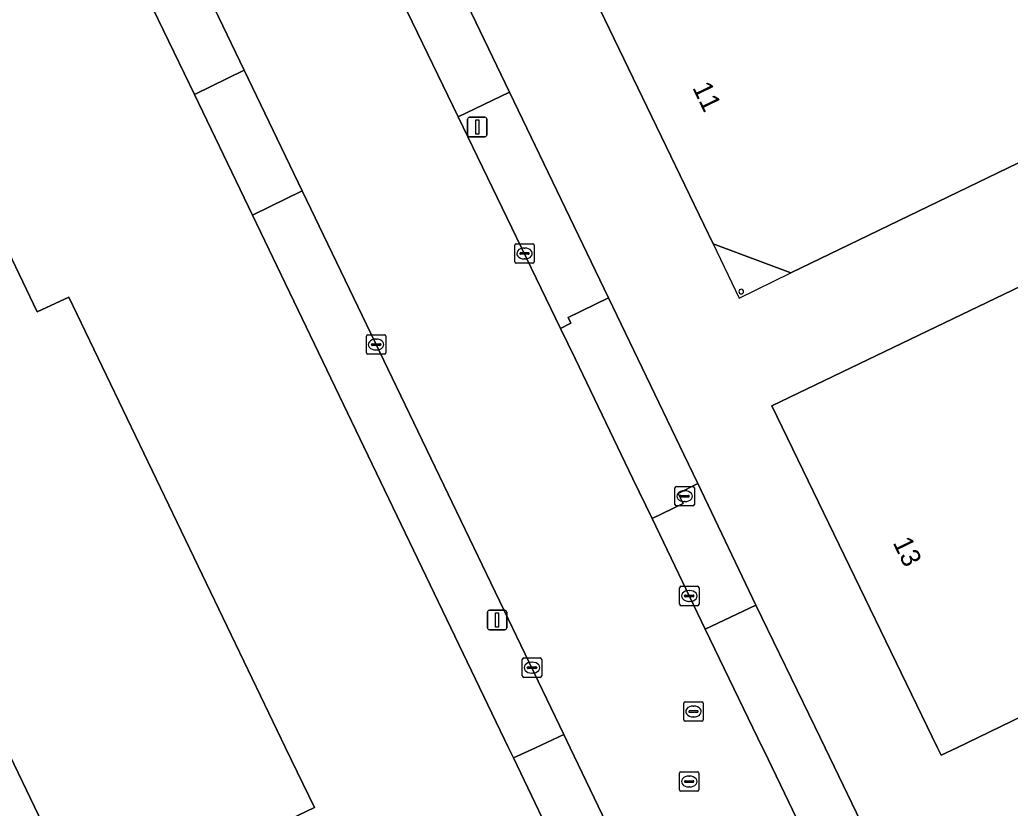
# Model space of a CAD drawing. Extents: x 157692 to 159674, y 381452 to 383291.
# Drawn here: x 158074.3 to 158125.3, y 381746.9 to 381787.5 of the extents above; entities that cross this region are included whole.
import ezdxf

# ---------------------------------------------------------------- set-up
doc = ezdxf.new("R2010")
doc.units = 0
for name, color, linetype in [('IMGEO_Brandkraan', 7, 'Continuous'), ('IMGEO_Erf', 7, 'Continuous'), ('IMGEO_Kolk', 7, 'Continuous'), ('IMGEO_Lichtmast', 7, 'Continuous'), ('IMGEO_Pand', 7, 'Continuous'), ('IMGEO_Pand_nummerreeks', 7, 'Continuous'), ('IMGEO_Pand_overbouw', 7, 'Continuous'), ('IMGEO_Rijbaan_lokaal_gesloten', 7, 'Continuous'), ('IMGEO_Rioolput', 7, 'Continuous'), ('IMGEO_Voetpad_open', 7, 'Continuous')]:
    doc.layers.add(name, color=color, linetype=linetype)

msp = doc.modelspace()

# ---------------------------------------------------------------- linework, layer by layer
at = {"layer": 'IMGEO_Brandkraan'}
for p, q in [((158108.057, 381762.52), (158108.057, 381763.372)), ((158108.132, 381763.446), (158108.984, 381763.446)), ((158108.545, 381763.226), (158108.57, 381763.226)), ((158109.058, 381763.372), (158109.058, 381762.52)), ((158108.316, 381762.94), (158108.316, 381762.952)), ((158108.754, 381762.903), (158108.356, 381762.903)), ((158108.359, 381762.989), (158108.757, 381762.989)), ((158108.568, 381762.666), (158108.543, 381762.666)), ((158108.8, 381762.952), (158108.8, 381762.94)), ((158108.984, 381762.446), (158108.132, 381762.446))]:
    msp.add_line(p, q, dxfattribs=at)
for points in [[(158108.057, 381762.52), (158108.057, 381763.372)], [(158108.132, 381763.446), (158108.984, 381763.446)], [(158109.058, 381763.372), (158109.058, 381762.52)], [(158108.984, 381762.446), (158108.132, 381762.446)]]:
    msp.add_lwpolyline(points, dxfattribs=at)
for centre, radius, start, end in [((158108.134, 381763.37), 0.0765, 91.552, 178.448), ((158108.134, 381763.37), 0.0765, 91.552, 178.448), ((158108.982, 381763.37), 0.0765, 1.552, 88.448), ((158108.982, 381763.37), 0.0765, 1.552, 88.448), ((158108.356, 381762.949), 0.0403, 85.8775, 175.7526), ((158108.353, 381762.939), 0.0366, 178.938, 274.7102), ((158108.757, 381762.946), 0.043, 264.8664, 352.4533), ((158108.761, 381762.951), 0.0386, 1.7309, 96.639), ((158108.134, 381762.522), 0.0765, 181.552, 268.448), ((158108.134, 381762.522), 0.0765, 181.552, 268.448), ((158108.982, 381762.522), 0.0765, 271.552, 358.448), ((158108.982, 381762.522), 0.0765, 271.552, 358.448)]:
    msp.add_arc(centre, radius, start, end, dxfattribs=at)
for centre, major_axis, ratio, start_param, end_param in [((158108.544, 381762.946), (-0.387, 0.002), 0.722429, 4.712389, 7.853982), ((158108.569, 381762.946), (-0.39, 0.002), 0.717154, 1.570796, 4.712389)]:
    msp.add_ellipse(centre, major_axis=major_axis, ratio=ratio, start_param=start_param, end_param=end_param, dxfattribs=at)
at = {"layer": 'IMGEO_Erf'}
for points in [[(158137.502, 381785.79), (158118.534, 381776.617), (158114.031, 381774.441), (158110.021, 381775.933), (158102.507, 381791.513), (158111.619, 381795.703), (158111.472, 381796), (158115.756, 381798.065), (158110.472, 381809.1), (158104.602, 381810.258), (158098.579, 381811.447), (158101.581, 381826.071)], [(158092.487, 381798.744), (158092.916, 381798.939), (158095.512, 381792.931), (158095.193, 381792.79), (158096.925, 381789.189), (158099.538, 381783.755), (158104.632, 381773.16), (158105.509, 381771.337), (158108.516, 381765.1), (158109.23, 381763.603), (158112.225, 381757.328), (158115.269, 381751.09), (158115.795, 381750), (158119.248, 381742.84), (158125.511, 381729.855), (158128.564, 381723.514), (158130.19, 381720.284), (158133.095, 381714.162), (158136.569, 381706.935)], [(158006.881, 381609.083), (158005.905, 381627.867), (158005.466, 381636.382), (158005.223, 381641.106), (158032.78, 381654.365), (158038.282, 381657.004), (158060.573, 381667.757), (158067.21, 381670.951), (158069.612, 381672.132), (158075.377, 381674.875), (158095.213, 381684.451), (158107.373, 381690.341), (158121.318, 381697.1), (158122.884, 381701.311), (158109.399, 381729.267), (158106.88, 381734.578), (158102.545, 381743.606), (158102.331, 381744.049), (158099.751, 381749.471), (158099.496, 381750), (158086.302, 381777.417), (158083.311, 381783.632), (158080.659, 381789.142)], [(158127.079, 381752.164), (158122.572, 381750), (158121.766, 381749.613), (158121.578, 381750), (158113.047, 381767.596), (158117.554, 381769.761), (158139.912, 381780.502)], [(158073.743, 381775.528), (158075.215, 381772.432), (158076.855, 381773.194), (158088.009, 381750), (158089.492, 381746.916), (158077.795, 381741.308), (158073.628, 381750)]]:
    msp.add_lwpolyline(points, dxfattribs=at)
for start, end in [(0, 180), (180, 0)]:
    msp.add_arc((158111.475, 381773.48), 0.12, start, end, dxfattribs=at)
at = {"layer": 'IMGEO_Kolk'}
for p, q in [((158099.813, 381775.016), (158099.813, 381775.868)), ((158099.888, 381775.942), (158100.74, 381775.942)), ((158100.814, 381775.868), (158100.814, 381775.016)), ((158100.072, 381775.436), (158100.072, 381775.448)), ((158100.51, 381775.399), (158100.112, 381775.399)), ((158100.115, 381775.485), (158100.513, 381775.485)), ((158100.301, 381775.722), (158100.326, 381775.722)), ((158100.556, 381775.448), (158100.556, 381775.436)), ((158100.74, 381774.942), (158099.888, 381774.942)), ((158100.324, 381775.162), (158100.299, 381775.162)), ((158092.245, 381771.253), (158093.097, 381771.253)), ((158092.17, 381770.327), (158092.17, 381771.179)), ((158092.429, 381770.747), (158092.429, 381770.759)), ((158092.867, 381770.71), (158092.469, 381770.71)), ((158092.472, 381770.796), (158092.87, 381770.796)), ((158092.658, 381771.033), (158092.683, 381771.033)), ((158092.913, 381770.759), (158092.913, 381770.747)), ((158093.171, 381771.179), (158093.171, 381770.327)), ((158093.097, 381770.253), (158092.245, 381770.253)), ((158092.681, 381770.473), (158092.656, 381770.473)), ((158108.297, 381757.384), (158108.297, 381758.236)), ((158108.372, 381758.31), (158109.224, 381758.31)), ((158108.785, 381758.09), (158108.81, 381758.09)), ((158109.298, 381758.236), (158109.298, 381757.384)), ((158108.556, 381757.804), (158108.556, 381757.816)), ((158108.994, 381757.767), (158108.596, 381757.767)), ((158108.599, 381757.853), (158108.997, 381757.853)), ((158108.808, 381757.53), (158108.783, 381757.53)), ((158109.04, 381757.816), (158109.04, 381757.804)), ((158109.224, 381757.31), (158108.372, 381757.31)), ((158100.197, 381753.692), (158100.197, 381754.544)), ((158100.272, 381754.618), (158101.124, 381754.618)), ((158100.685, 381754.398), (158100.71, 381754.398)), ((158101.198, 381754.544), (158101.198, 381753.692)), ((158100.456, 381754.112), (158100.456, 381754.124)), ((158100.894, 381754.075), (158100.496, 381754.075)), ((158100.499, 381754.161), (158100.897, 381754.161)), ((158100.94, 381754.124), (158100.94, 381754.112)), ((158101.124, 381753.618), (158100.272, 381753.618)), ((158100.708, 381753.838), (158100.683, 381753.838))]:
    msp.add_line(p, q, dxfattribs=at)
for points in [[(158099.813, 381775.016), (158099.813, 381775.868)], [(158099.888, 381775.942), (158100.74, 381775.942)], [(158100.814, 381775.868), (158100.814, 381775.016)], [(158100.74, 381774.942), (158099.888, 381774.942)], [(158092.245, 381771.253), (158093.097, 381771.253)], [(158092.17, 381770.327), (158092.17, 381771.179)], [(158093.171, 381771.179), (158093.171, 381770.327)], [(158093.097, 381770.253), (158092.245, 381770.253)], [(158108.297, 381757.384), (158108.297, 381758.236)], [(158108.372, 381758.31), (158109.224, 381758.31)], [(158109.298, 381758.236), (158109.298, 381757.384)], [(158109.224, 381757.31), (158108.372, 381757.31)], [(158100.197, 381753.692), (158100.197, 381754.544)], [(158100.272, 381754.618), (158101.124, 381754.618)], [(158101.198, 381754.544), (158101.198, 381753.692)], [(158101.124, 381753.618), (158100.272, 381753.618)]]:
    msp.add_lwpolyline(points, dxfattribs=at)
for centre, radius, start, end in [((158099.89, 381775.866), 0.0765, 91.552, 178.448), ((158099.89, 381775.866), 0.0765, 91.552, 178.448), ((158100.738, 381775.866), 0.0765, 1.552, 88.448), ((158100.738, 381775.866), 0.0765, 1.552, 88.448), ((158100.112, 381775.445), 0.0403, 85.8775, 175.7526), ((158100.109, 381775.435), 0.0366, 178.938, 274.7102), ((158100.513, 381775.442), 0.043, 264.8664, 352.4533), ((158100.517, 381775.447), 0.0386, 1.7309, 96.639), ((158099.89, 381775.018), 0.0765, 181.552, 268.448), ((158099.89, 381775.018), 0.0765, 181.552, 268.448), ((158100.738, 381775.018), 0.0765, 271.552, 358.448), ((158100.738, 381775.018), 0.0765, 271.552, 358.448), ((158092.247, 381771.177), 0.0765, 91.552, 178.448), ((158092.247, 381771.177), 0.0765, 91.552, 178.448), ((158093.095, 381771.177), 0.0765, 1.552, 88.448), ((158093.095, 381771.177), 0.0765, 1.552, 88.448), ((158092.469, 381770.756), 0.0403, 85.8775, 175.7526), ((158092.466, 381770.746), 0.0366, 178.938, 274.7102), ((158092.87, 381770.753), 0.043, 264.8664, 352.4533), ((158092.874, 381770.758), 0.0386, 1.7309, 96.639), ((158092.247, 381770.329), 0.0765, 181.552, 268.448), ((158092.247, 381770.329), 0.0765, 181.552, 268.448), ((158093.095, 381770.329), 0.0765, 271.552, 358.448), ((158093.095, 381770.329), 0.0765, 271.552, 358.448), ((158108.374, 381758.234), 0.0765, 91.552, 178.448), ((158108.374, 381758.234), 0.0765, 91.552, 178.448), ((158109.222, 381758.234), 0.0765, 1.552, 88.448), ((158109.222, 381758.234), 0.0765, 1.552, 88.448), ((158108.596, 381757.813), 0.0403, 85.8775, 175.7526), ((158108.593, 381757.803), 0.0366, 178.938, 274.7102), ((158108.997, 381757.81), 0.043, 264.8664, 352.4533), ((158109.001, 381757.815), 0.0386, 1.7309, 96.639), ((158108.374, 381757.386), 0.0765, 181.552, 268.448), ((158108.374, 381757.386), 0.0765, 181.552, 268.448), ((158109.222, 381757.386), 0.0765, 271.552, 358.448), ((158109.222, 381757.386), 0.0765, 271.552, 358.448), ((158100.274, 381754.542), 0.0765, 91.552, 178.448), ((158100.274, 381754.542), 0.0765, 91.552, 178.448), ((158101.122, 381754.542), 0.0765, 1.552, 88.448), ((158101.122, 381754.542), 0.0765, 1.552, 88.448), ((158100.496, 381754.121), 0.0403, 85.8775, 175.7526), ((158100.493, 381754.111), 0.0366, 178.938, 274.7102), ((158100.897, 381754.118), 0.043, 264.8664, 352.4533), ((158100.901, 381754.123), 0.0386, 1.7309, 96.639), ((158100.274, 381753.694), 0.0765, 181.552, 268.448), ((158100.274, 381753.694), 0.0765, 181.552, 268.448), ((158101.122, 381753.694), 0.0765, 271.552, 358.448), ((158101.122, 381753.694), 0.0765, 271.552, 358.448)]:
    msp.add_arc(centre, radius, start, end, dxfattribs=at)
for centre, major_axis, ratio, start_param, end_param in [((158100.3, 381775.442), (-0.387, 0.002), 0.722429, 4.712389, 7.853982), ((158100.325, 381775.442), (-0.39, 0.002), 0.717154, 1.570796, 4.712389), ((158092.657, 381770.753), (-0.387, 0.002), 0.722429, 4.712389, 7.853982), ((158092.682, 381770.753), (-0.39, 0.002), 0.717154, 1.570796, 4.712389), ((158108.784, 381757.81), (-0.387, 0.002), 0.722429, 4.712389, 7.853982), ((158108.809, 381757.81), (-0.39, 0.002), 0.717154, 1.570796, 4.712389), ((158100.684, 381754.118), (-0.387, 0.002), 0.722429, 4.712389, 7.853982), ((158100.709, 381754.118), (-0.39, 0.002), 0.717154, 1.570796, 4.712389)]:
    msp.add_ellipse(centre, major_axis=major_axis, ratio=ratio, start_param=start_param, end_param=end_param, dxfattribs=at)
at = {"layer": 'IMGEO_Lichtmast'}
for p, q in [((158097.484, 381782.455), (158098.274, 381782.455)), ((158098.274, 381782.455), (158097.484, 381782.455)), ((158097.384, 381781.555), (158097.384, 381782.355)), ((158097.384, 381782.355), (158097.384, 381781.555)), ((158098.374, 381782.355), (158098.374, 381781.555)), ((158098.374, 381781.555), (158098.374, 381782.355)), ((158098.274, 381781.455), (158097.484, 381781.455)), ((158097.484, 381781.455), (158098.274, 381781.455)), ((158098.405, 381756.172), (158098.405, 381756.972)), ((158098.405, 381756.972), (158098.405, 381756.172)), ((158098.505, 381757.072), (158099.295, 381757.072)), ((158099.295, 381757.072), (158098.505, 381757.072)), ((158099.395, 381756.972), (158099.395, 381756.172)), ((158099.395, 381756.172), (158099.395, 381756.972)), ((158099.295, 381756.072), (158098.505, 381756.072)), ((158098.505, 381756.072), (158099.295, 381756.072))]:
    msp.add_line(p, q, dxfattribs=at)
for points in [[(158097.804, 381782.33), (158097.954, 381782.33), (158097.954, 381781.58), (158097.804, 381781.58), (158097.804, 381782.33)], [(158098.825, 381756.947), (158098.975, 381756.947), (158098.975, 381756.197), (158098.825, 381756.197), (158098.825, 381756.947)]]:
    msp.add_lwpolyline(points, dxfattribs=at)
for centre, start, end in [((158097.484, 381782.355), 90, 180), ((158097.484, 381782.355), 90, 180), ((158098.274, 381782.355), 0, 90), ((158098.274, 381782.355), 360, 90), ((158097.484, 381781.555), 180, 270), ((158097.484, 381781.555), 180, 270), ((158098.274, 381781.555), 270, 0), ((158098.274, 381781.555), 270, 0), ((158098.505, 381756.972), 90, 180), ((158098.505, 381756.972), 90, 180), ((158099.295, 381756.972), 0, 90), ((158099.295, 381756.972), 360, 90), ((158098.505, 381756.172), 180, 270), ((158098.505, 381756.172), 180, 270), ((158099.295, 381756.172), 270, 0), ((158099.295, 381756.172), 270, 0)]:
    msp.add_arc(centre, 0.1, start, end, dxfattribs=at)
at = {"layer": 'IMGEO_Pand'}
for points in [[(158145.318, 381803.988), (158145.367, 381804.226), (158142.32, 381810.52), (158130.35, 381804.77), (158115.87, 381797.75), (158111.619, 381795.703), (158102.507, 381791.513), (158110.021, 381775.933), (158114.031, 381774.441), (158118.534, 381776.617), (158137.502, 381785.79), (158139.912, 381780.502), (158153.628, 381787.091), (158150.957, 381792.296)], [(158148.721, 381762.553), (158153.283, 381764.743), (158157.545, 381755.963), (158152.984, 381753.772), (158153.078, 381753.578), (158153.136, 381753.458), (158166.776, 381760.006), (158162.361, 381769.101), (158153.628, 381787.091), (158139.912, 381780.502), (158117.554, 381769.761), (158113.047, 381767.596), (158121.578, 381750), (158121.766, 381749.613), (158122.572, 381750), (158127.079, 381752.164)]]:
    msp.add_lwpolyline(points, close=True, dxfattribs=at)
msp.add_lwpolyline([(158073.628, 381750), (158077.795, 381741.308), (158089.492, 381746.916), (158088.009, 381750), (158076.855, 381773.194), (158075.215, 381772.432), (158073.743, 381775.528)], dxfattribs=at)
for start, end in [(0, 180), (180, 0)]:
    msp.add_arc((158111.475, 381773.48), 0.12, start, end, dxfattribs=at)
at = {"layer": 'IMGEO_Pand_overbouw'}
msp.add_lwpolyline([(158114.031, 381774.441), (158110.021, 381775.933), (158111.372, 381773.149)], close=True, dxfattribs=at)
at = {"layer": 'IMGEO_Rijbaan_lokaal_gesloten'}
for points in [[(158116.624, 381741.577), (158112.648, 381749.831), (158112.566, 381750), (158109.618, 381756.099), (158106.881, 381761.797), (158105.898, 381763.844), (158102.919, 381770.034), (158102.171, 381771.58), (158096.9, 381782.478), (158094.275, 381787.906), (158092.511, 381791.553), (158091.569, 381793.508), (158089.774, 381797.512)], [(158083.226, 381790.381), (158085.876, 381784.875), (158088.862, 381778.671), (158102.332, 381750.683), (158102.661, 381750), (158104.936, 381745.273)]]:
    msp.add_lwpolyline(points, dxfattribs=at)
at = {"layer": 'IMGEO_Rioolput'}
for p, q in [((158108.587, 381752.362), (158109.439, 381752.362)), ((158108.512, 381751.436), (158108.512, 381752.288)), ((158108.771, 381751.856), (158108.771, 381751.868)), ((158108.814, 381751.905), (158109.212, 381751.905)), ((158109, 381752.142), (158109.025, 381752.142)), ((158109.255, 381751.868), (158109.255, 381751.856)), ((158109.513, 381752.288), (158109.513, 381751.436)), ((158109.439, 381751.362), (158108.587, 381751.362)), ((158109.209, 381751.819), (158108.811, 381751.819)), ((158109.023, 381751.582), (158108.998, 381751.582)), ((158108.295, 381747.831), (158108.295, 381748.683)), ((158108.37, 381748.757), (158109.222, 381748.757)), ((158108.554, 381748.251), (158108.554, 381748.263)), ((158108.597, 381748.3), (158108.995, 381748.3)), ((158108.783, 381748.537), (158108.808, 381748.537)), ((158109.038, 381748.263), (158109.038, 381748.251)), ((158109.296, 381748.683), (158109.296, 381747.831)), ((158109.222, 381747.757), (158108.37, 381747.757)), ((158108.992, 381748.214), (158108.594, 381748.214)), ((158108.806, 381747.977), (158108.781, 381747.977))]:
    msp.add_line(p, q, dxfattribs=at)
for points in [[(158108.587, 381752.362), (158109.439, 381752.362)], [(158108.512, 381751.436), (158108.512, 381752.288)], [(158109.513, 381752.288), (158109.513, 381751.436)], [(158109.439, 381751.362), (158108.587, 381751.362)], [(158108.295, 381747.831), (158108.295, 381748.683)], [(158108.37, 381748.757), (158109.222, 381748.757)], [(158109.296, 381748.683), (158109.296, 381747.831)], [(158109.222, 381747.757), (158108.37, 381747.757)]]:
    msp.add_lwpolyline(points, dxfattribs=at)
for centre, radius, start, end in [((158108.589, 381752.286), 0.0765, 91.552, 178.448), ((158108.589, 381752.286), 0.0765, 91.552, 178.448), ((158109.437, 381752.286), 0.0765, 1.552, 88.448), ((158109.437, 381752.286), 0.0765, 1.552, 88.448), ((158108.811, 381751.865), 0.0403, 85.8775, 175.7526), ((158108.808, 381751.855), 0.0366, 178.938, 274.7102), ((158109.212, 381751.862), 0.043, 264.8664, 352.4533), ((158109.216, 381751.867), 0.0386, 1.7309, 96.639), ((158108.589, 381751.438), 0.0765, 181.552, 268.448), ((158108.589, 381751.438), 0.0765, 181.552, 268.448), ((158109.437, 381751.438), 0.0765, 271.552, 358.448), ((158109.437, 381751.438), 0.0765, 271.552, 358.448), ((158108.372, 381748.681), 0.0765, 91.552, 178.448), ((158108.372, 381748.681), 0.0765, 91.552, 178.448), ((158108.594, 381748.26), 0.0403, 85.8775, 175.7526), ((158108.999, 381748.262), 0.0386, 1.7309, 96.639), ((158109.22, 381748.681), 0.0765, 1.552, 88.448), ((158109.22, 381748.681), 0.0765, 1.552, 88.448), ((158108.372, 381747.833), 0.0765, 181.552, 268.448), ((158108.372, 381747.833), 0.0765, 181.552, 268.448), ((158108.591, 381748.25), 0.0366, 178.938, 274.7102), ((158108.995, 381748.257), 0.043, 264.8664, 352.4533), ((158109.22, 381747.833), 0.0765, 271.552, 358.448), ((158109.22, 381747.833), 0.0765, 271.552, 358.448)]:
    msp.add_arc(centre, radius, start, end, dxfattribs=at)
for centre, major_axis, ratio, start_param, end_param in [((158108.999, 381751.862), (-0.387, 0.002), 0.722429, 4.712389, 7.853982), ((158109.024, 381751.862), (-0.39, 0.002), 0.717154, 1.570796, 4.712389), ((158108.782, 381748.257), (-0.387, 0.002), 0.722429, 4.712389, 7.853982), ((158108.807, 381748.257), (-0.39, 0.002), 0.717154, 1.570796, 4.712389)]:
    msp.add_ellipse(centre, major_axis=major_axis, ratio=ratio, start_param=start_param, end_param=end_param, dxfattribs=at)
at = {"layer": 'IMGEO_Voetpad_open'}
msp.add_lwpolyline([(158080.659, 381789.142), (158083.311, 381783.632), (158085.876, 381784.875), (158083.226, 381790.381)], dxfattribs=at)
for points in [[(158096.9, 381782.478), (158099.538, 381783.755), (158096.925, 381789.189), (158094.275, 381787.906)], [(158086.302, 381777.417), (158088.862, 381778.671), (158085.876, 381784.875), (158083.311, 381783.632)], [(158099.538, 381783.755), (158096.9, 381782.478), (158102.171, 381771.58), (158102.706, 381771.852), (158102.56, 381772.154), (158104.632, 381773.16)], [(158086.302, 381777.417), (158099.496, 381750), (158099.751, 381749.471), (158100.878, 381750), (158102.332, 381750.683), (158088.862, 381778.671)], [(158105.509, 381771.337), (158104.632, 381773.16), (158102.56, 381772.154), (158102.706, 381771.852), (158102.171, 381771.58), (158102.919, 381770.034), (158105.898, 381763.844), (158106.881, 381761.797), (158108.489, 381762.563), (158108.224, 381763.088), (158109.23, 381763.603), (158108.516, 381765.1)], [(158109.23, 381763.603), (158108.224, 381763.088), (158108.489, 381762.563), (158106.881, 381761.797), (158109.618, 381756.099), (158112.225, 381757.328)], [(158119.248, 381742.84), (158115.795, 381750), (158115.269, 381751.09), (158112.225, 381757.328), (158109.618, 381756.099), (158112.566, 381750), (158112.648, 381749.831), (158116.624, 381741.577)], [(158102.332, 381750.683), (158100.878, 381750), (158099.751, 381749.471), (158102.331, 381744.049), (158104.936, 381745.273), (158102.661, 381750)]]:
    msp.add_lwpolyline(points, close=True, dxfattribs=at)

# ---------------------------------------------------------------- texts
at = {"layer": 'IMGEO_Pand_nummerreeks'}
for s, rotation, p in [('11', 295.7657, (158108.938, 381783.986)), ('13', 295.8631, (158119.26, 381760.559))]:
    msp.add_text(s, height=1, rotation=rotation, dxfattribs=at).set_placement(p)

doc.saveas('drawing.dxf')
